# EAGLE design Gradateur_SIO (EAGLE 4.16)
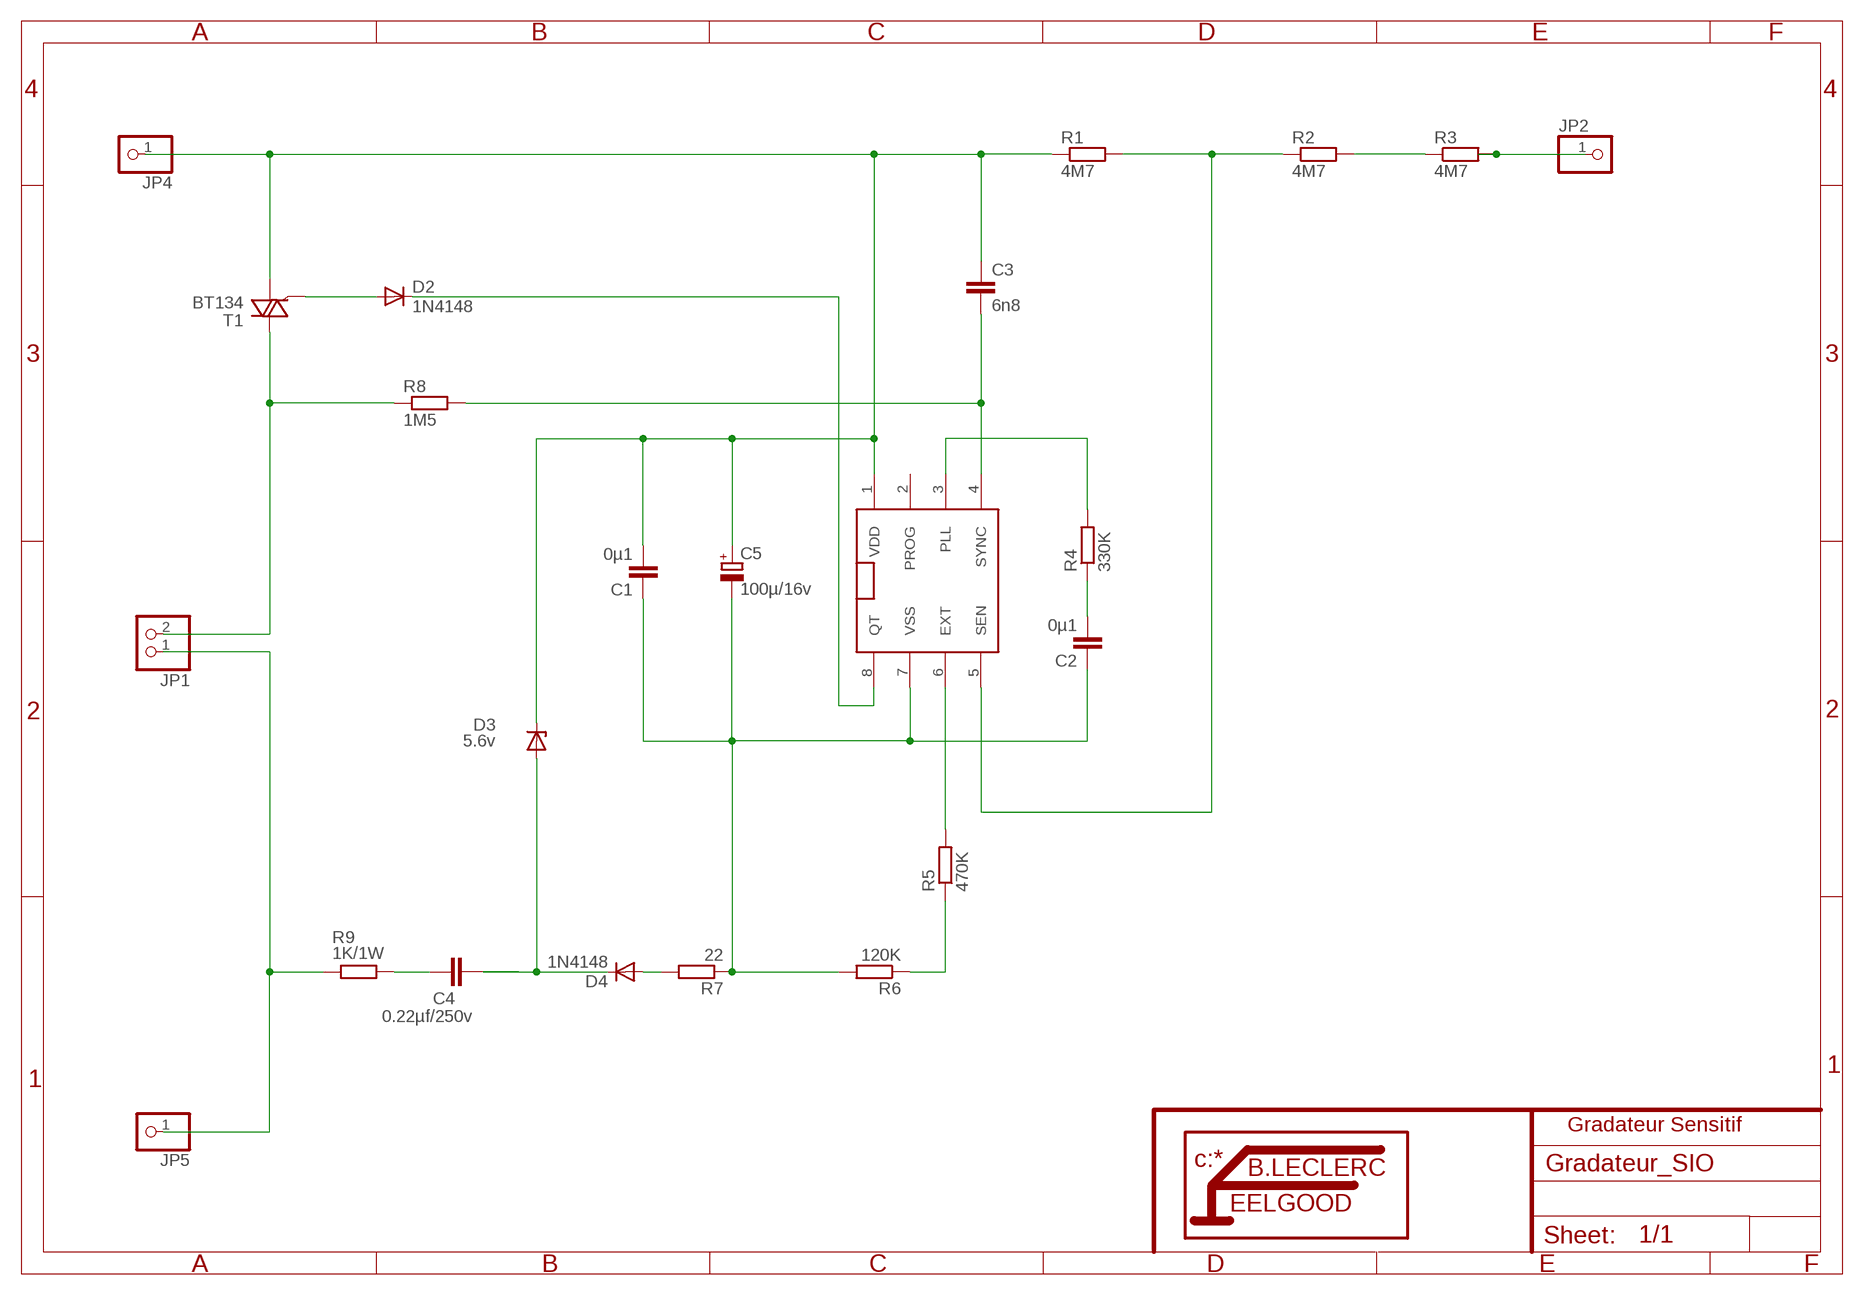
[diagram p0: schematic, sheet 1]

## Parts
C1  0µ1  C-EUC1206  [C1206]
C2  0µ1  C-EUC1206  [C1206]
C3  6n8  C-EUC1206  [C1206]
C4  0.22µf/250v  C-EU102-054X133  [C102-054X133]
C5  100µ/16v  CPOL-EUE2.5-6  [E2,5-6]
D2  1N4148  DIODE-SOD106-R  [SOD106-R]
D3  5.6v  ZENER-DIODEF126-10  [F126Z10]
D4  1N4148  DIODE-SOD106-R  [SOD106-R]
JP1  PINHD-1X2  [1X02]
JP2  PINHD-1X1  [1X01]
JP4  PINHD-1X1  [1X01]
JP5  PINHD-1X1  [1X01]
R1  4M7  R-EU_M1206  [M1206]
R2  4M7  R-EU_M1206  [M1206]
R3  4M7  R-EU_M1206  [M1206]
R4  330K  R-EU_M1206  [M1206]
R5  470K  R-EU_M1206  [M1206]
R6  120K  R-EU_M1206  [M1206]
R7  22  R-EU_M1206  [M1206]
R8  1M5  R-EU_M1206  [M1206]
R9  1K/1W  R-EU_0411/12  [0411/12]
T1  BT134  BT134-600E  [SOT82S]
U1  SLB0587SIO  [SLB0587SIO]

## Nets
N$1: C1.2 C3.1 C5.+ D3.C JP4.1 R1.1 T1.C(A1) U1.1(VDD)
N$2: JP1.2 R8.1 T1.A(A2)
N$3: JP1.1 JP5.1 R9.1
N$4: C4.1 R9.2
N$6: C4.2 D3.A D4.C
N$7: D4.A R7.2
N$8: C1.1 C2.1 C5.- R6.2 R7.1 U1.7(VSS)
N$9: R5.1 R6.1
N$11: R5.2 U1.6(EXT)
N$14: C2.2 R4.1
N$15: R4.2 U1.3(PLL)
N$16: R2.2 R3.1
N$17: R1.2 R2.1 U1.5(SEN)
N$19: C3.2 R8.2 U1.4(SYNC)
N$21: D2.A T1.G
N$22: D2.C U1.8(QT)
N$23: JP2.1 R3.2
Unconnected: U1.2(PROG)

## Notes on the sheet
- Gradateur Sensitif

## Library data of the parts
C1-C4 = rcl:C-EU: CAPACITOR, European symbol
C5 = rcl:CPOL-EU: POLARIZED CAPACITOR, European symbol
D2 D4 = diode:DIODE-: DIODE
D3 = diode:ZENER-DIODE: Z-Diode
JP1 = pinhead:PINHD-1X2: PIN HEADER
JP2 JP4 JP5 = pinhead:PINHD-1X1: PIN HEADER
R1-R9 = rcl:R-EU_: RESISTOR, European symbol
T1 = triac:BT134-600E
U1 = Siemens:SLB0587SIO

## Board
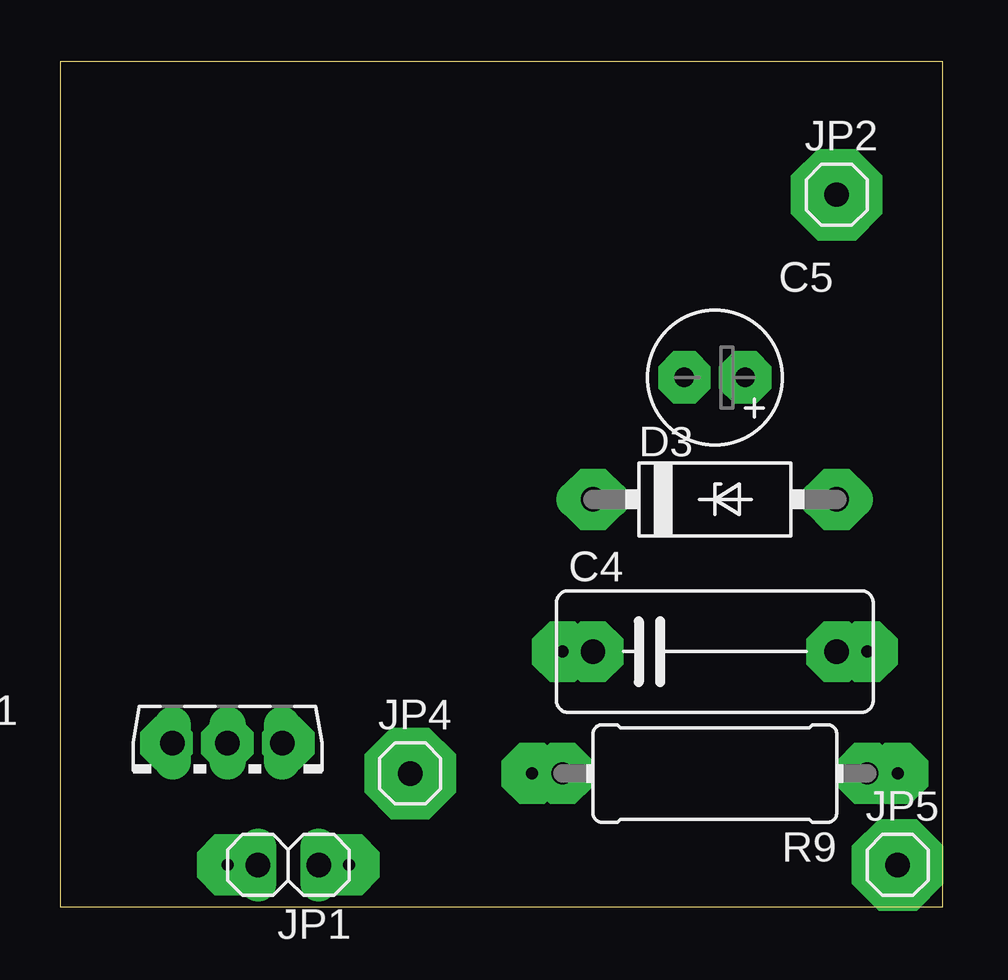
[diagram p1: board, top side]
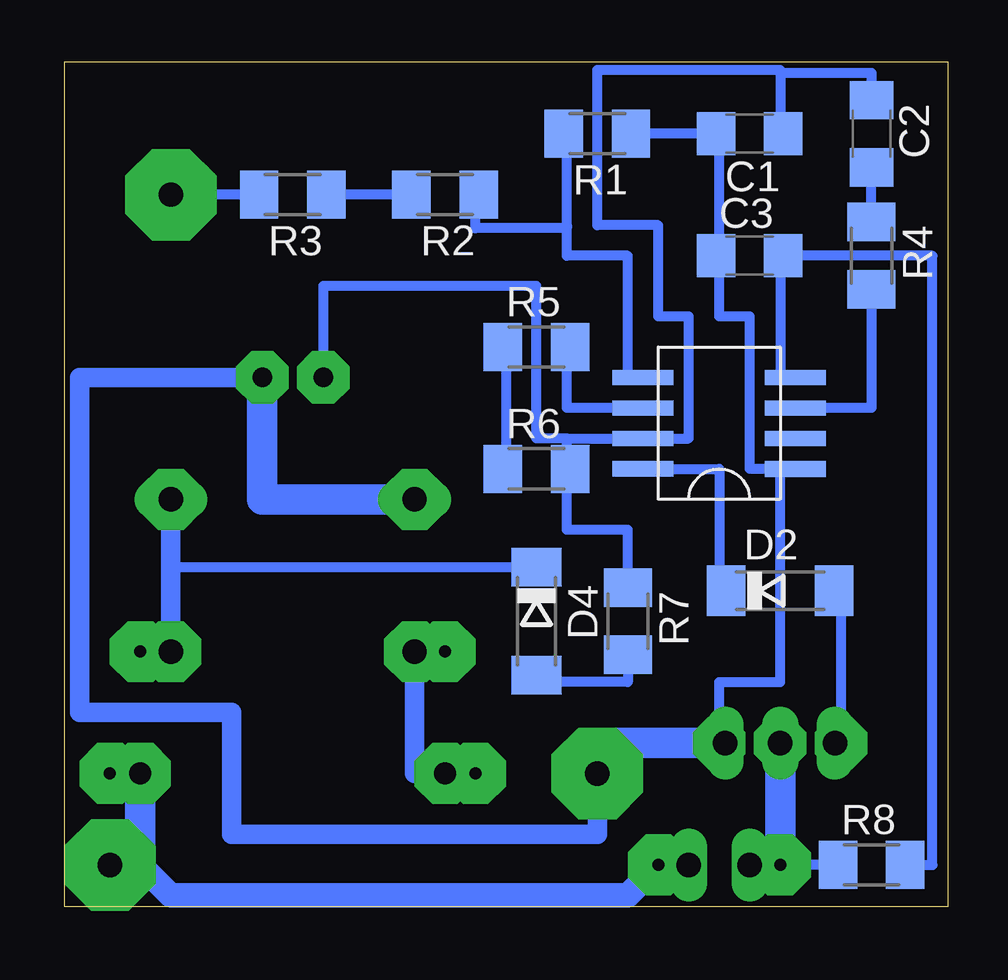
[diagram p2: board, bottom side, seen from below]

Size 36.81 x 35.23 mm. Coordinates in mm from the lower left corner, seen from the top.
Outline: 0,0 36.81,0 36.81,35.23 0,35.23 0,0
Copper layers (1*16): Top 0.035mm / dielectric 1.5mm / Bottom 0.035mm
Design rules "default": minimum track width 10mil, minimum drill 24mil, track to track 8mil, track to pad 8mil, pad to pad 8mil, via to via 8mil, smd to smd 8mil, copper to edge 40mil, drill to drill 8mil, minimum pad ring 10mil, minimum via ring 8mil, stop-mask expansion 4mil, vias tented up to drill 0mil, thermal gap 10mil

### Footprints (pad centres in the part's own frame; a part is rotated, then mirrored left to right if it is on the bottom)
C1206 = smd 1.6 x 1.8: 1 -1.4,0; 2 1.4,0
C102-054X133 = drill 1.016 octagon: 1 -5.08,0; 2 5.08,0
E2,5-6 = drill 0.813 pad 1.6 round: + -1.27,0 | drill 0.813 pad 1.6 octagon: - 1.27,0
SOD106-R = smd 1.6 x 2.1: A 2.25,0; C -2.25,0
F126Z10 = drill 1.016 long: A 5.08,0; C -5.08,0
1X02 = drill 1.016 long: 1 -1.27,0; 2 1.27,0
1X01 = drill 1.016 octagon: 1 0,0
M1206 = smd 1.6 x 2: 1 -1.4,0; 2 1.4,0
0411/12 = drill 0.914 octagon: 1 -6.35,0; 2 6.35,0
SOT82S = drill 1.016 long: A 0,-1.27; C -2.286,-1.27; G 2.286,-1.27
SLB0587SIO = smd 0.66 x 1.27: 1 1.27,-2.54; P$8 1.27,-3.81 | smd 0.635 x 1.27: 2 2.54,-2.54; 3 3.81,-2.54; 4 5.08,-2.54; 5 5.08,2.54; 6 3.81,2.54; 7 2.54,2.54; 8 1.27,2.54; P$10 2.54,-3.81; P$11 3.81,-3.81; P$12 5.08,-3.81; P$13 5.08,3.81; P$14 3.81,3.81; P$15 2.54,3.81; P$16 1.27,3.81

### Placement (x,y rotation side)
C1  8.25,32.22 180 bottom
C2  3.17,32.22 270 bottom
C3  8.25,27.14 0 bottom
C4  27.3,10.63 0 top
C5  27.3,22.06 180 top
D2  6.98,13.17 0 bottom
D3  27.3,16.98 0 top
D4  17.14,11.9 270 bottom
JP1  9.52,1.74 180 top
JP2  32.38,29.68 0 top
JP4  14.6,5.55 0 top
JP5  34.92,1.74 0 top
R1  14.6,32.22 180 bottom
R2  20.95,29.68 180 bottom
R3  27.3,29.68 180 bottom
R4  3.17,27.14 270 bottom
R5  17.14,23.33 0 bottom
R6  17.14,18.25 0 bottom
R7  13.33,11.9 270 bottom
R8  3.17,1.74 0 bottom
R9  27.3,5.55 180 top
T1  6.98,5.55 180 top
U1  9.52,16.98 90 bottom

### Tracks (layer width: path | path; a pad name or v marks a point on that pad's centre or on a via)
N$1
  Bottom 0.406: 9.52,6.82 9.52,9.36 6.98,9.36 U1.1 8.25,18.25 8.25,24.6 9.52,24.6 9.52,27.14 | 9.52,27.14 9.52,32.22 C1.2 R1.1 13.33,32.22 | 9.52,27.14 C3.1
  Bottom 0.813: JP4.1 14.6,3.01 29.84,3.01 29.84,8.09 36.19,8.09 36.19,22.06 C5.+
  Bottom 1.27: T1.C 9.52,6.82 14.6,6.82 JP4.1 | D3.C 28.57,16.98 C5.+
N$2  (via drill 0.5 pad 2.54)
  Bottom 0.406: R8.1 v6.98,1.74 JP1.2
  Bottom 1.27: T1.A v6.98,1.74 JP1.2
N$3  (via drill 0.5 pad 2.54)
  Bottom 1.016: JP1.1 v12.06,1.74 13.33,0.47 32.38,0.47 33.65,1.74
  Bottom 1.27: JP5.1 33.65,1.74 R9.1
N$4
  Bottom 0.813: R9.2 22.22,5.55 C4.1
N$5  (via drill 0.5 pad 3.81)
  other vias: 32.38,29.68
N$6
  Bottom 0.406: D4.C 32.38,14.15 32.38,14.44
  Bottom 0.813: C4.2 32.38,14.44 D3.A
N$7
  Bottom 0.406: R7.2 13.33,9.36 17.14,9.36 D4.A
N$8
  Bottom 0.406: 15.87,19.52 U1.7 10.79,19.52 10.79,24.6 12.06,24.6 12.06,28.41 14.6,28.41 14.6,34.89 6.98,34.89 6.98,34.76 | 15.87,18.25 15.87,19.52 | C5.- 26.03,25.87 17.14,25.87 17.14,19.52 15.87,19.52 | C1.1 6.98,32.22 6.98,34.76 | R7.1 13.33,15.71 15.87,15.71 15.87,18.25 | 15.87,18.25 R6.2 | C2.1 3.17,34.76 6.98,34.76
N$9
  Bottom 0.406: R6.1 18.41,18.25 18.41,23.33 R5.1
N$10  (via drill 0.5 pad 3.81)
  other vias: 34.92,1.74
N$11
  Bottom 0.406: U1.6 15.87,20.79 15.87,23.33 R5.2
N$12  (via drill 0.5 pad 3.81)
  other vias: 14.6,5.55
N$13  (via drill 0.5 pad 2.54)
  other vias: 22.22,10.63
N$14
  Bottom 0.406: 3.17,30.95 C2.2 R4.1
N$15
  Bottom 0.406: R4.2 3.17,20.79 U1.3
N$16
  Bottom 0.406: 26.03,29.68 R3.1 R2.2
N$17
  Bottom 0.406: U1.5 13.33,22.06 13.33,27.14 15.87,27.14 15.87,28.41 | R2.1 19.68,29.68 19.68,28.28 15.87,28.28 15.87,28.41 | R1.2 15.87,32.22 15.87,28.41
N$18  (via drill 0.5 pad 2.54)
  other vias: 32.38,10.63
N$19
  Bottom 0.406: U1.4 6.98,27.14 0.63,27.14 0.63,1.74 R8.2
  Bottom 1.27: 6.98,27.14 C3.2
N$20  (via drill 0.5 pad 2.54)
  other vias: 20.95,5.55
N$21  (via drill 0.5 pad 2.18)
  Bottom 0.406: D2.A 4.44,13.17 v4.44,6.82 T1.G
N$22
  Bottom 0.406: U1.8 9.52,18.25 9.52,13.17 D2.C
N$23
  Bottom 0.406: R3.2 JP2.1
N$24  (via drill 0.5 pad 2.54)
  other vias: 33.65,5.55
N$25  (via drill 0.5 pad 2.54)
  other vias: 19.68,5.55
N$26  (via drill 0.5 pad 2.54)
  other vias: 34.92,5.55
N$27  (via drill 0.5 pad 2.54)
  other vias: 20.95,10.63
N$28  (via drill 0.5 pad 2.54)
  other vias: 33.65,10.63
N$29  (via drill 0.5 pad 2.54)
  other vias: 22.22,16.98
N$30  (via drill 0.5 pad 2.54)
  other vias: 32.38,16.98
N$31  (via drill 0.5 pad 2.18)
  other vias: 6.98,6.82
N$32  (via drill 0.5 pad 2.18)
  other vias: 9.52,6.82
N$33  (via drill 0.5 pad 2.18)
  other vias: 26.03,22.06
N$34  (via drill 0.5 pad 2.18)
  other vias: 28.57,22.06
